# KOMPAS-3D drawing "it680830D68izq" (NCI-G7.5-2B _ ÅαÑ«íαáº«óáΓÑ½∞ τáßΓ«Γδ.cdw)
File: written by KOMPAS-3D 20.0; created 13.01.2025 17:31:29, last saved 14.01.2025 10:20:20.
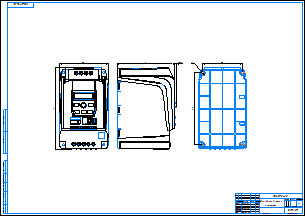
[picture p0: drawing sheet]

Sheet 1: A1, landscape

Document properties: Автор: admin; Полное имя файла: C:\Уралов Работа\Уралов (локальная)\ПЧ\! Китай 3Д-модель NCI\NCI 11-15 4B\NCI 11-15 4B.m3d

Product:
- Part/product: it680830D68izq

Title block, sheet 1: Наименование: Преобразователь / частоты; designation: NCI-G7.5-2B; Количество листов документа: 1; organisation: INSTART; cell 10: Согласовано; Форматы листов документа: A1; stored path: P:\INSTART\Технический отдел\ОР\Прочие задачи\КД на номенклатурный ряд\КД на типоразмеры ПЧ\NCI\NCI-...-4B\NCI-G11_P15-4B\NCI-G11_P15-4B _ Преобразователь частоты.cdw; Разработал: Уралов Д.А.; Проверил: Андреев Н.В.; Подписал: Смелков Ж.Е.; Утвердил: Ефремов И.Н.; Разработал, date: 13.01.25

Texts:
  Поверхности
  it680830D68izq
  it680830D68izq it680830D68izq
Dimensions and other numbers on the sheet: 1:1; 1; 13.01.25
